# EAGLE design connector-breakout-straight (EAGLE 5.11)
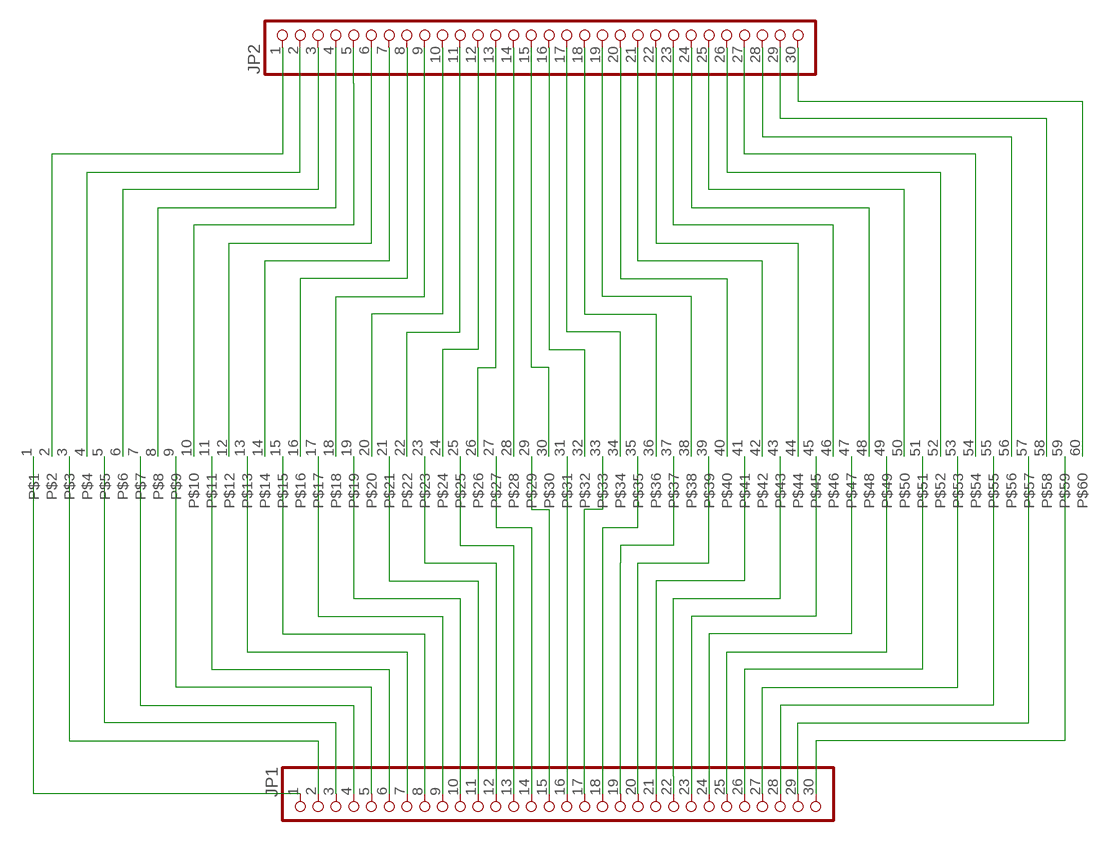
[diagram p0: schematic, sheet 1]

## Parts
JP1  PINHD-1X30  [1X30]
JP2  PINHD-1X30  [1X30]
U$1  FPC-60-CHUMBY  [FH28-60S-0.5SH(05)]

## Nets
N$1: JP1.1 U$1.1
N$2: JP1.2 U$1.3
N$3: JP1.3 U$1.5
N$4: JP1.4 U$1.7
N$5: JP1.5 U$1.9
N$6: JP1.6 U$1.11
N$7: JP1.7 U$1.13
N$8: JP1.8 U$1.15
N$9: JP1.9 U$1.17
N$10: JP1.10 U$1.19
N$11: JP1.11 U$1.21
N$12: JP1.12 U$1.23
N$13: JP1.13 U$1.25
N$14: JP1.14 U$1.27
N$15: JP1.15 U$1.29
N$16: JP1.16 U$1.31
N$17: JP1.18 U$1.35
N$18: JP1.19 U$1.37
N$19: JP1.17 U$1.33
N$20: JP1.20 U$1.39
N$21: JP1.21 U$1.41
N$22: JP1.22 U$1.43
N$23: JP1.23 U$1.45
N$24: JP1.24 U$1.47
N$25: JP1.25 U$1.49
N$26: JP1.26 U$1.51
N$27: JP1.27 U$1.53
N$28: JP1.28 U$1.55
N$29: JP1.29 U$1.57
N$30: JP1.30 U$1.59
N$31: JP2.30 U$1.60
N$32: JP2.29 U$1.58
N$33: JP2.28 U$1.56
N$34: JP2.27 U$1.54
N$35: JP2.26 U$1.52
N$36: JP2.25 U$1.50
N$37: JP2.24 U$1.48
N$38: JP2.23 U$1.46
N$39: JP2.22 U$1.44
N$40: JP2.21 U$1.42
N$41: JP2.20 U$1.40
N$42: JP2.19 U$1.38
N$43: JP2.18 U$1.36
N$44: JP2.17 U$1.34
N$45: JP2.16 U$1.32
N$46: JP2.15 U$1.30
N$47: JP2.14 U$1.28
N$48: JP2.13 U$1.26
N$49: JP2.12 U$1.24
N$50: JP2.11 U$1.22
N$51: JP2.10 U$1.20
N$52: JP2.9 U$1.18
N$53: JP2.8 U$1.16
N$54: JP2.7 U$1.14
N$55: JP2.6 U$1.12
N$56: JP2.5 U$1.10
N$57: JP2.4 U$1.8
N$58: JP2.3 U$1.6
N$59: JP2.2 U$1.4
N$60: JP2.1 U$1.2

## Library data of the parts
JP1 JP2 = pinhead:PINHD-1X30: PIN HEADER
U$1 = trl:FPC-60-CHUMBY

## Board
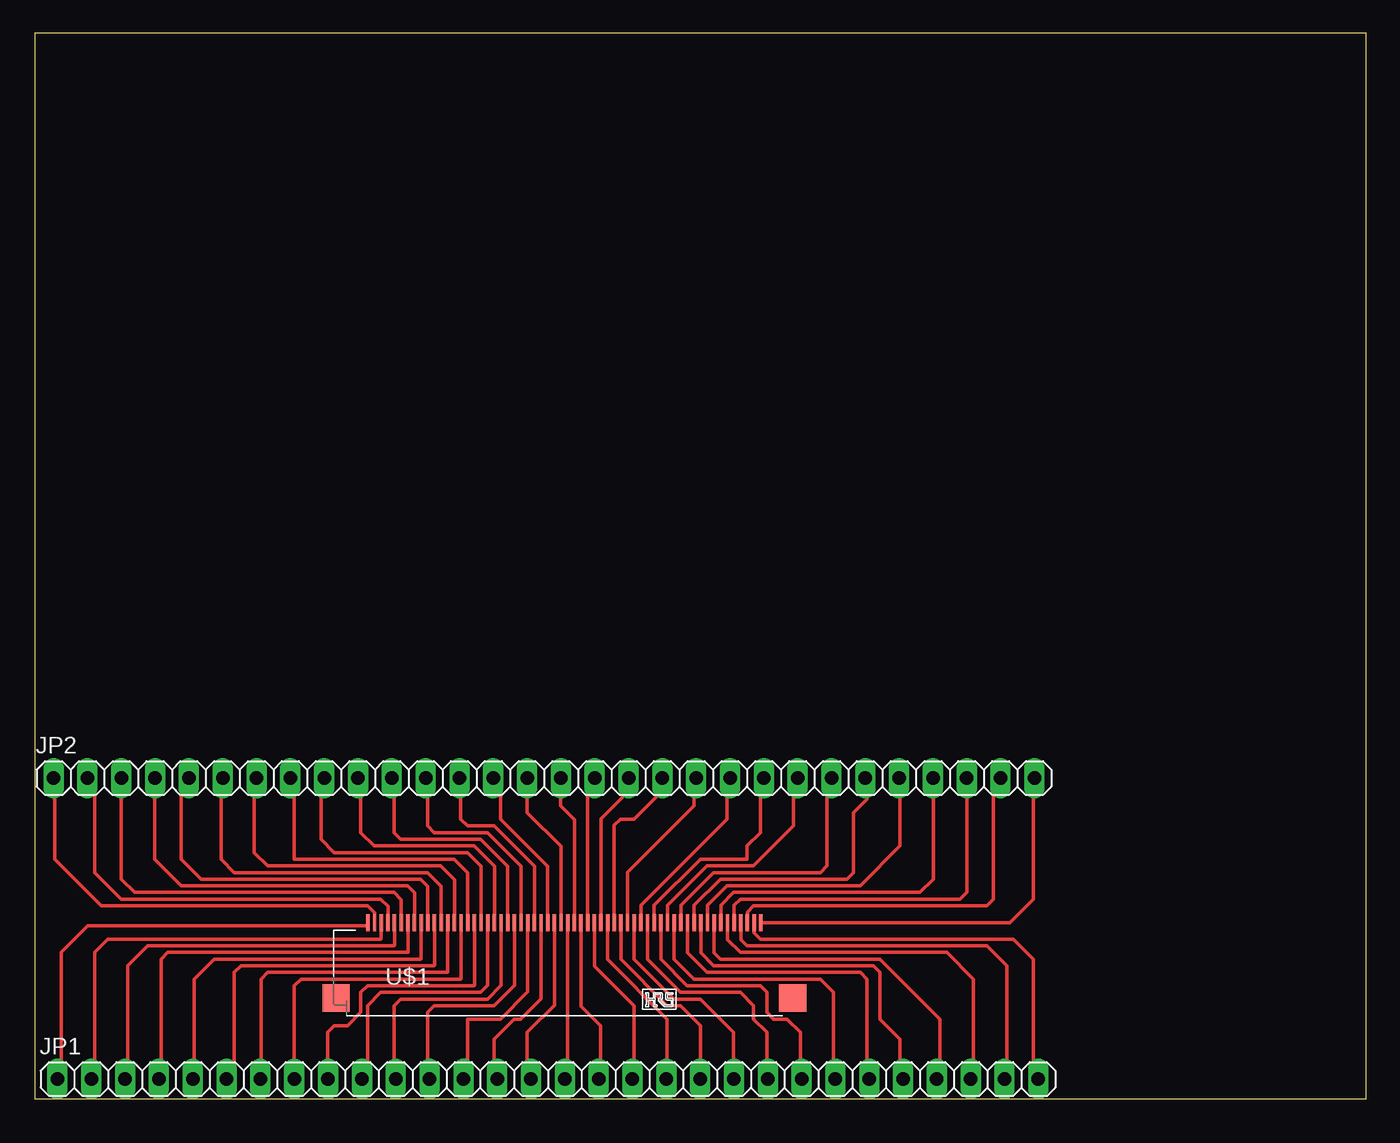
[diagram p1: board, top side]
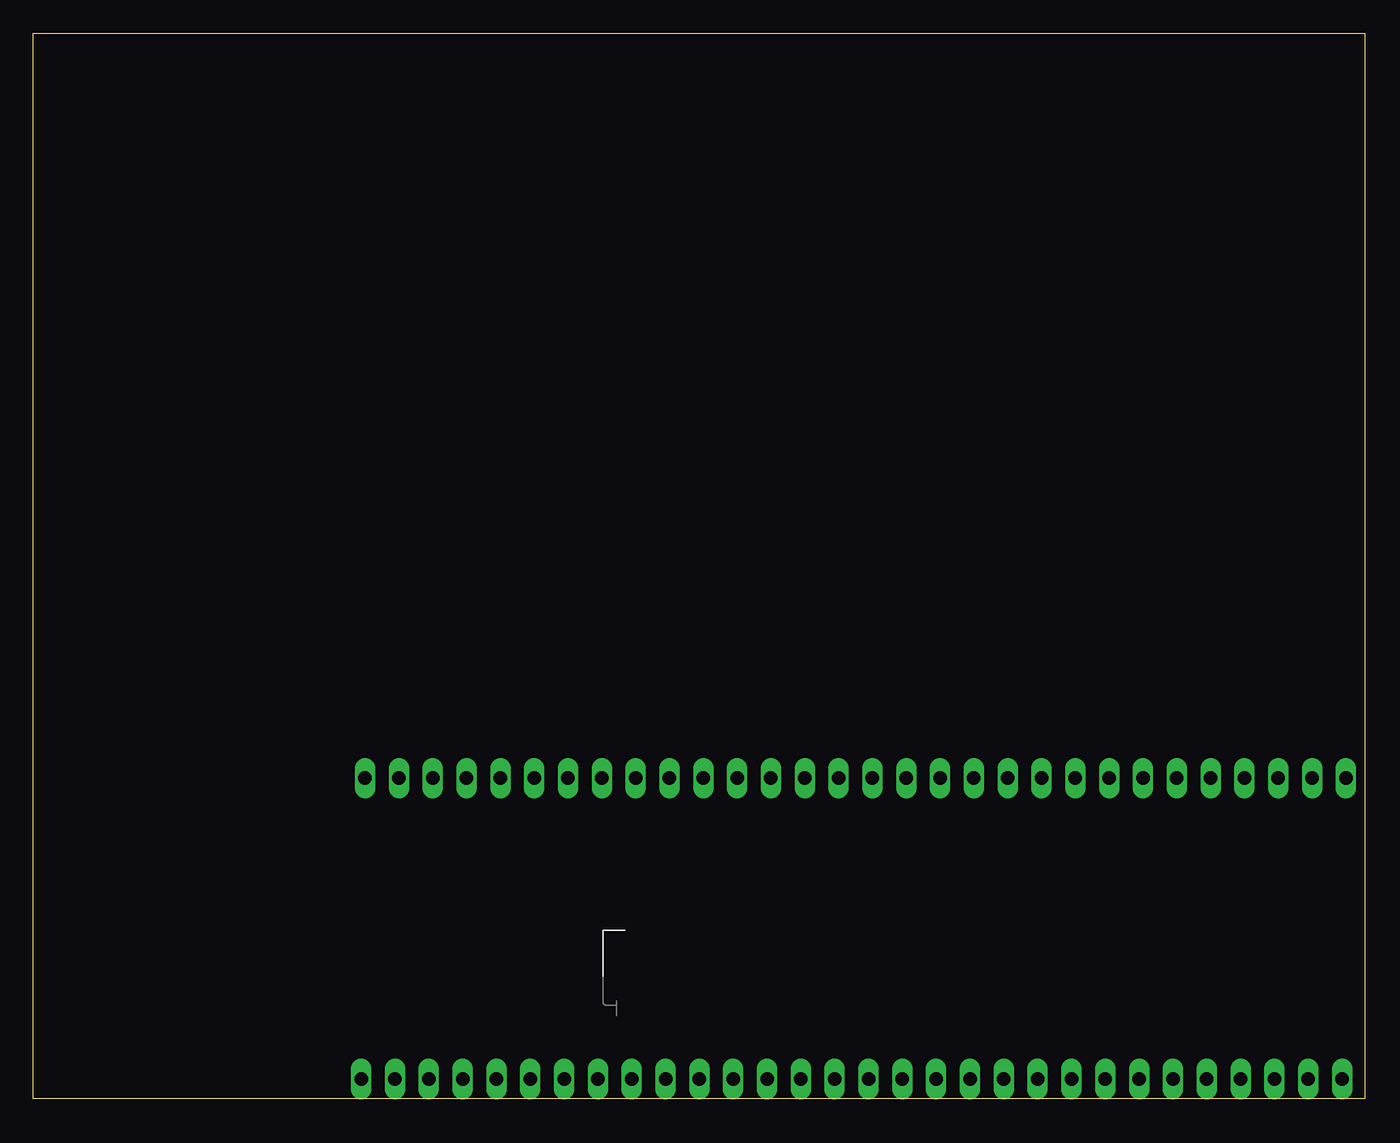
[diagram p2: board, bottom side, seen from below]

Size 100 x 80 mm. Coordinates in mm from the lower left corner, seen from the top.
Outline: 0,0 100,0 100,80 0,80 0,0
Copper layers (1*16): Top 0.035mm / dielectric 1.5mm / Bottom 0.035mm
Design rules "default *": minimum track width 0.3mm, minimum drill 0.7mm, track to track 8mil, track to pad 8mil, pad to pad 8mil, via to via 8mil, smd to smd 8mil, copper to edge 40mil, drill to drill 8mil, minimum pad ring 10mil, minimum via ring 8mil, stop-mask expansion 4mil, vias tented up to drill 0mil, thermal gap 10mil

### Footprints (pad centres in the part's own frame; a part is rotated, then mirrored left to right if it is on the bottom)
1X30 = drill 1.016 long: 1 -36.83,0; 2 -34.29,0; 3 -31.75,0; 4 -29.21,0; 5 -26.67,0; 6 -24.13,0; 7 -21.59,0; 8 -19.05,0; 9 -16.51,0; 10 -13.97,0; 11 -11.43,0; 12 -8.89,0; 13 -6.35,0; 14 -3.81,0; 15 -1.27,0; 16 1.27,0; 17 3.81,0; 18 6.35,0; 19 8.89,0; 20 11.43,0; 21 13.97,0; 22 16.51,0; 23 19.05,0; 24 21.59,0; 25 24.13,0; 26 26.67,0; 27 29.21,0; 28 31.75,0; 29 34.29,0; 30 36.83,0
FH28-60S-0.5SH(05) = smd 0.254 x 1.3: 1 -12.25,3.5; 2 -11.75,3.5; 3 -11.25,3.5; 4 -10.75,3.5; 5 -10.25,3.5; 6 -9.75,3.5; 7 -9.25,3.5; 8 -8.75,3.5; 9 -8.25,3.5; 10 -7.75,3.5; 11 -7.25,3.5; 12 -6.75,3.5; 13 -6.25,3.5; 14 -5.75,3.5; 15 -5.25,3.5; 16 -4.75,3.5; 17 -4.25,3.5; 18 -3.75,3.5; 19 -3.25,3.5; 20 -2.75,3.5; 21 -2.25,3.5; 22 -1.75,3.5; 23 -1.25,3.5; 24 -0.75,3.5; 25 -0.25,3.5; 26 0.25,3.5; 27 0.75,3.5; 28 1.25,3.5; 29 1.75,3.5; 30 2.25,3.5; 31 2.75,3.5; 32 3.25,3.5; 33 3.75,3.5; 34 4.25,3.5; 35 4.75,3.5; 36 5.25,3.5; 37 5.75,3.5; 38 6.25,3.5; 39 6.75,3.5; 40 7.25,3.5; 41 7.75,3.5; 42 8.25,3.5; 43 8.75,3.5; 44 9.25,3.5; 45 9.75,3.5; 46 10.25,3.5; 47 10.75,3.5; 48 11.25,3.5; 49 11.75,3.5; 50 12.25,3.5; 51 12.75,3.5; 52 13.25,3.5; 53 13.75,3.5; 54 14.25,3.5; 55 14.75,3.5; 56 15.25,3.5; 57 15.75,3.5; 58 16.25,3.5; 59 16.75,3.5; 60 17.25,3.5 | smd 2.032 x 2.032: M1 19.65,-2.15; M2 -14.65,-2.15

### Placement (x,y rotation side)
JP1  38.55,1.49 0 top
JP2  38.25,24.08 0 top
U$1  37.28,9.73 0 top

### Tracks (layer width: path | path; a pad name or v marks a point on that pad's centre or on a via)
N$1
  Top 0.254: U$1.1 25,13.23 25,13 4,13 2,11 2,1.77 JP1.1
N$2
  Top 0.254: U$1.3 26.03,12.03 26,12 5.5,12 4.5,11 4.5,1.73 JP1.2
N$3
  Top 0.254: U$1.5 27.03,11.53 27,11.5 8.5,11.5 7,10 7,1.69 JP1.3
N$4
  Top 0.254: U$1.7 28.03,11.03 28,11 10,11 9.5,10.5 9.5,1.65 JP1.4
N$5
  Top 0.254: U$1.9 29.03,10.53 29,10.5 13.5,10.5 12,9 12,1.61 JP1.5
N$6
  Top 0.254: U$1.11 30.03,10.03 30,10 15.5,10 15,9.5 15,2.07 JP1.6
N$7
  Top 0.254: U$1.13 31.03,9.53 31,9.5 17.5,9.5 17,9 17,1.53 JP1.7
N$8
  Top 0.254: U$1.15 32.03,9.03 32,9 20,9 19.5,8.5 JP1.8
N$9
  Top 0.254: U$1.17 33.03,8.53 33,8.5 25,8.5 24.5,8 24.5,6.5 23.5,5.5 22.5,5.5 22,5 22,1.53 JP1.9
N$10
  Top 0.254: U$1.19 34.03,8.53 33.5,8 26,8 25,7 25,1.91 JP1.10
N$11
  Top 0.254: U$1.21 35.03,8.53 34,7.5 27.5,7.5 27,7 27,1.61 JP1.11
N$12
  Top 0.254: U$1.23 36.03,8.53 34.5,7 30,7 29.5,6.5 29.5,1.65 JP1.12
N$13
  Top 0.254: U$1.25 37.03,8.03 35,6 32.5,6 32.5,1.79 JP1.13
N$14
  Top 0.254: U$1.27 38.03,7.53 36.5,6 36,6 34.5,4.5 34.5,1.73 JP1.14
N$15
  Top 0.254: U$1.29 39.03,7.03 37,5 37,1.77 JP1.15
N$16
  Top 0.254: U$1.31 40.03,1.7 JP1.16
N$17
  Top 0.254: U$1.35 42.03,9.97 45,7 45,1.59 JP1.18
N$18
  Top 0.254: U$1.37 43.03,10.47 47.5,6 47.5,1.55 JP1.19
N$19
  Top 0.254: U$1.33 41.03,6.97 42.5,5.5 42.5,1.63 JP1.17
N$20
  Top 0.254: U$1.39 44.03,10.47 47.5,7 48.5,7 50,5.5 50,1.51 JP1.20
N$21
  Top 0.254: U$1.41 45.03,10.47 46,9.5 48,7.5 50,7.5 52.5,5 52.5,1.51 JP1.21
N$22
  Top 0.254: U$1.43 46.03,10.47 48.5,8 53,8 54,7 54,6 55,5 55,1.55 JP1.22
N$23
  Top 0.254: U$1.45 47.03,10.47 49,8.5 54.5,8.5 55,8 55,6.5 55.5,6 56.5,6 57.5,5 57.5,2 58,1.5 JP1.23
N$24
  Top 0.254: U$1.47 48.03,10.47 49.5,9 59,9 60,8 60,1.63 JP1.24
N$25
  Top 0.254: U$1.49 49.03,10.97 50.5,9.5 62,9.5 62.5,9 62.5,1.67 JP1.25
N$26
  Top 0.254: U$1.51 50.03,10.97 51,10 63,10 63.5,9.5 63.5,6 65,4.5 65,1.71 JP1.26
N$27
  Top 0.254: U$1.53 51.03,10.97 51.5,10.5 63.5,10.5 68,6 68,1.73 JP1.27
N$28
  Top 0.254: U$1.55 52.03,11.97 53,11 68.5,11 70.5,9 70.5,1.69 JP1.28
N$29
  Top 0.254: U$1.57 53.03,11.97 53.5,11.5 71.5,11.5 73,10 73,1.65 JP1.29
N$30
  Top 0.254: U$1.59 54.03,12.47 54.5,12 73.5,12 75,10.5 75,1.87 JP1.30
N$31
  Top 0.254: U$1.60 73.23,13.23 75,15 75,24 JP2.30
N$32
  Top 0.254: U$1.58 53.53,14.03 54,14.5 71.5,14.5 72,15 72,23.54 JP2.29
N$33
  Top 0.254: U$1.56 52.53,14.53 53,15 69.5,15 70,15.5 JP2.28
N$34
  Top 0.254: U$1.54 51.53,14.53 52.5,15.5 66.5,15.5 67.5,16.5 67.5,24.05 JP2.27
N$35
  Top 0.254: U$1.52 50.53,14.53 52,16 62,16 65,19 65,24.01 JP2.26
N$36
  Top 0.254: U$1.50 49.53,14.53 51.5,16.5 61,16.5 61.5,17 61.5,21.5 62.5,22.5 62.5,23.97 JP2.25
N$37
  Top 0.254: U$1.48 48.53,14.53 51,17 59,17 59.5,17.5 59.5,23.74 JP2.24
N$38
  Top 0.254: U$1.46 47.53,14.53 50.5,17.5 54,17.5 57,20.5 57,23.78 JP2.23
N$39
  Top 0.254: U$1.44 46.53,14.53 50,18 53.5,18 53.5,19 54.5,20 54.5,23.82 JP2.22
N$40
  Top 0.254: U$1.42 45.53,14.53 51,20 52,21 52,23.86 JP2.21
N$41
  Top 0.254: U$1.40 44.53,17.03 47.5,20 49.5,22 49.5,23.9 JP2.20
N$42
  Top 0.254: U$1.38 43.53,20.53 44,21 45,21 47,23 47,23.94 JP2.19
N$43
  Top 0.254: U$1.36 42.53,21.03 44.5,23 44.5,23.19 JP2.18
N$44
  Top 0.254: U$1.34 41.53,24.05 JP2.17
N$45
  Top 0.254: U$1.32 40.53,20.97 39.5,22 39.5,24.06 JP2.16
N$46
  Top 0.254: U$1.30 39.53,18.97 37,21.5 37,24.07 JP2.15
N$47
  Top 0.254: U$1.28 38.53,17.47 35,21 35,23.53 JP2.14
N$48
  Top 0.254: U$1.26 37.53,17.47 34.5,20.5 32.5,20.5 32,21 32,23.99 JP2.13
N$49
  Top 0.254: U$1.24 36.53,17.47 34,20 30,20 29.5,20.5 29.5,23.95 JP2.12
N$50
  Top 0.254: U$1.22 35.53,17.47 33.5,19.5 27.5,19.5 27,20 27,23.91 JP2.11
N$51
  Top 0.254: U$1.20 34.53,17.47 33,19 25.5,19 24.5,20 24.5,23.87 JP2.10
N$52
  Top 0.254: U$1.18 33.53,17.47 32.5,18.5 22.5,18.5 21.5,19.5 21.5,23.84 JP2.9
N$53
  Top 0.254: U$1.16 32.53,16.97 31.5,18 19.5,18 19.5,23.79 JP2.8
N$54
  Top 0.254: U$1.14 31.53,16.47 30.5,17.5 17.5,17.5 16.5,18.5 16.5,23.92 JP2.7
N$55
  Top 0.254: U$1.12 30.53,15.97 29.5,17 15,17 14,18 14,23.96 JP2.6
N$56
  Top 0.254: U$1.10 29.53,15.97 29,16.5 12.5,16.5 11,18 11,23.5 JP2.5
N$57
  Top 0.254: U$1.8 28.53,15.47 28,16 11,16 9,18 9,24.04 JP2.4
N$58
  Top 0.254: U$1.6 27.53,14.97 27,15.5 7.5,15.5 6.5,16.5 JP2.3
N$59
  Top 0.254: U$1.4 26.53,14.47 26,15 6.5,15 4.5,17 4.5,23.55 JP2.2
N$60
  Top 0.254: U$1.2 25.53,13.97 25.5,14 25,14.5 5,14.5 1.5,18 1.5,24.01 JP2.1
